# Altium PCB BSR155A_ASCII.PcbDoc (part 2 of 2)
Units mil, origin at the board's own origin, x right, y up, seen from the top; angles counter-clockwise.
Board outline 3250 x 2500 mil, 4 copper layers (Top Layer, MidLayer1, MidLayer2, Bottom Layer), stack 59.8 mil thick; 70 components, 25 nets, 149 pads, 70 vias.
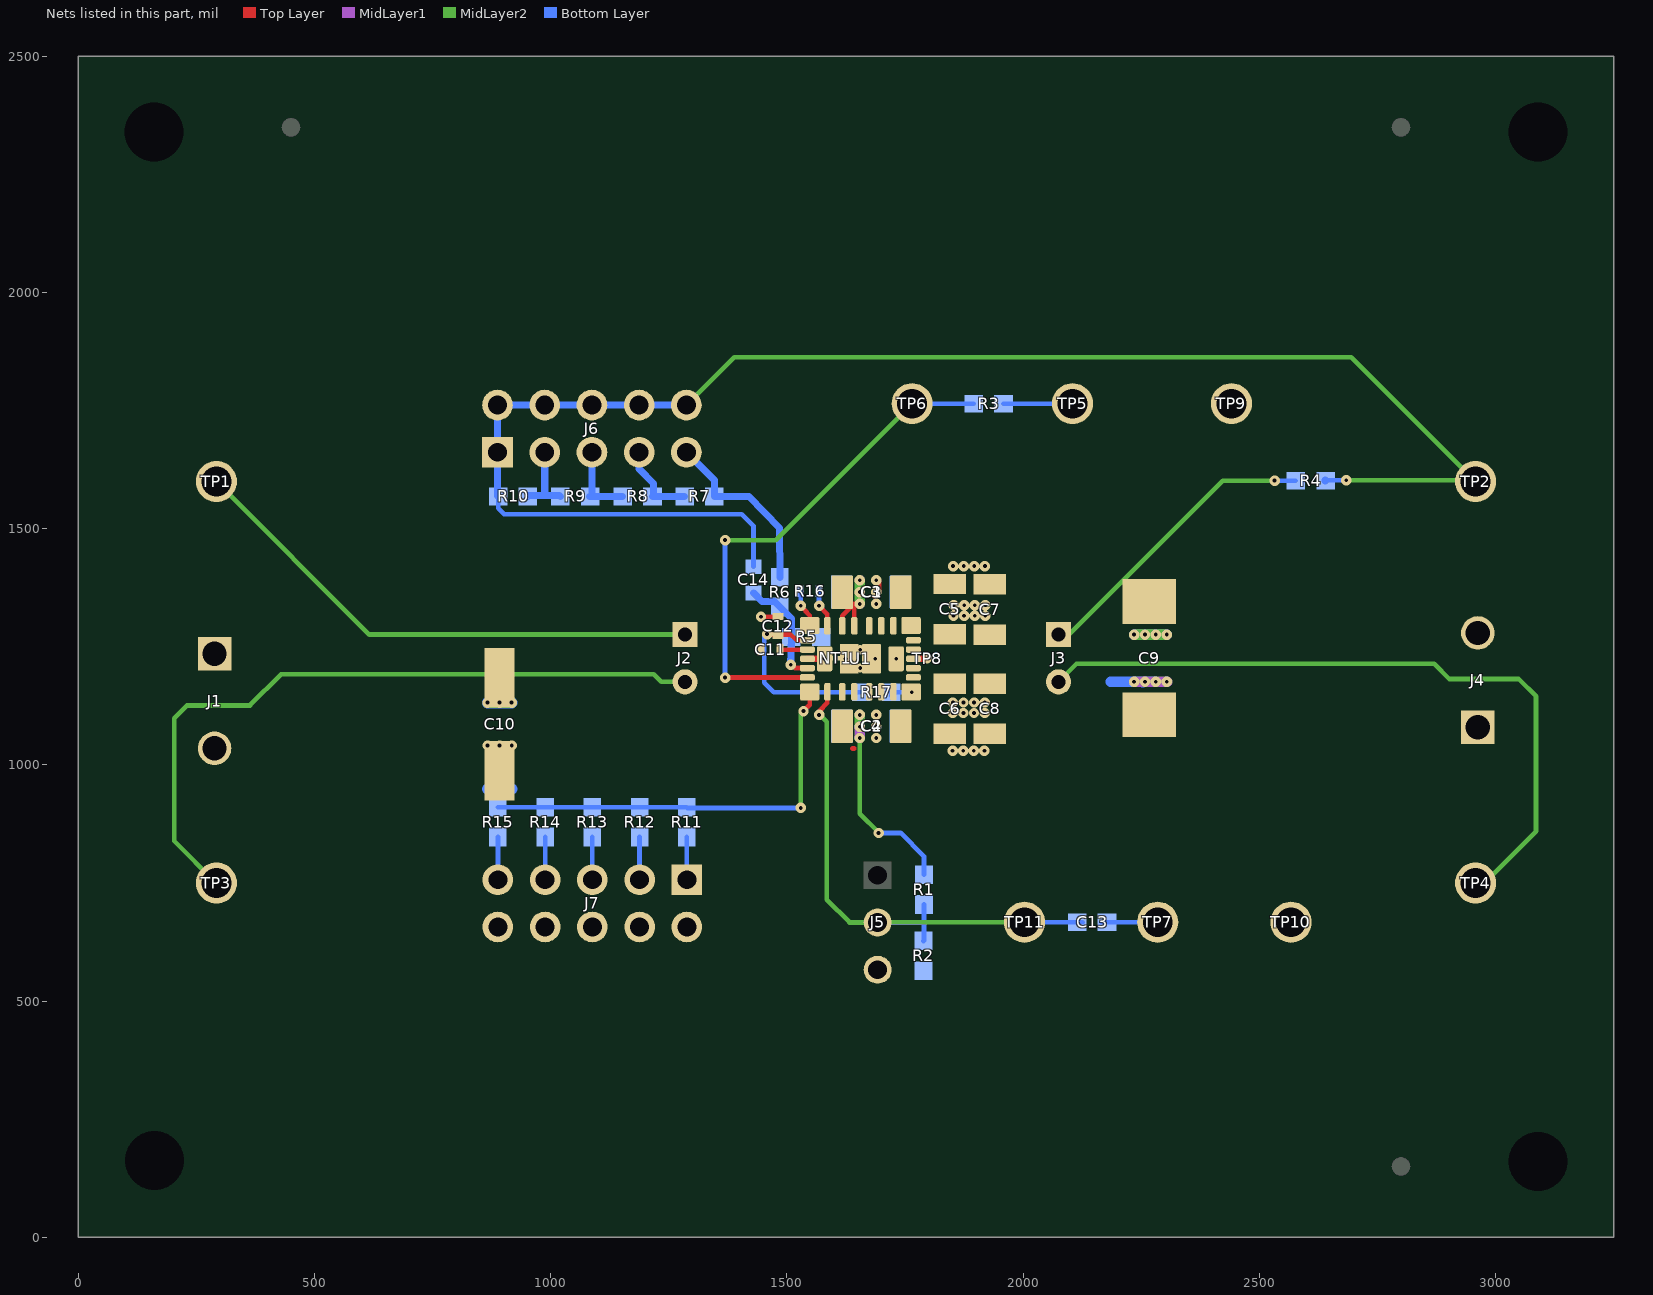
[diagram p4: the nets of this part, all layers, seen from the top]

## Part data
C1 C2 C3 C4: library part CMP-0089881-1, "4.7µF ±10% 100V Ceramic Capacitor X7S 1206 (3216 Metric)"
C5 C6 C7 C8: library part CMP-0008656-2, "CAP, CERM, 47 uF, 25 V, +/- 20%, X5R, 1206_190"
C9: library part CMP-0064986-2, "CAP, Tantalum Polymer, 330 uF, 10 V,+/- 20%, 0.035 ohm, 7343-40 SMD"
C10: library part CMP-0011204-2, "CAP, AL, 47 uF, 50 V, +/- 20%, 0.68 ohm, AEC-Q200 Grade 2, SMD"
C11: library part CMP-0006347-2, "CAP, CERM, 1 uF, 16 V, +/- 10%, X5R, 0402"
C12: library part CMP-0006608-2, "CAP, CERM, 1 uF, 25 V, +/- 10%, X5R, 0402"
C13: library part CMP-0006845-4, "CAP, CERM, 1000 pF, 50 V, +/- 5%, X7R, 0603"
C14: library part CMP-0007396-4, "CAP, CERM, 4700 pF, 16 V, +/- 10%, X7R, 0603"
FID1 FID2 FID3 FID4 FID5 FID6: library part CMP-0077181-1, "Fiducial mark.  There is nothing to buy or mount."
J1 J4: library part CMP-0074959-1, "Terminal Block, 2x1, 5.08mm, TH"
J2 J3: library part CMP-0055017-1, "Socket Strip, 2x1, 100mil, Black, Tin, TH"
J5: library part CMP-0002338-1, "Header, 100mil, 3x1, Tin, TH"
J6 J7: library part CMP-0054550-2, "Header, 100mil, 5x2, Tin, TH"
Logo1: library part CMP-0074838-1, "Texas Instrument Corporate Signature"
Logo2: library part CMP-0074844-1
Logo3: library part CMP-0074847-1, "FCC_disclaimer"
Logo4: library part CMP-0074769-1
NT1: library part CMP-0078142-3, "Single point connection between nets."
R1: library part CMP-0022408-4, "RES, 402 k, 1%, 0.1 W, AEC-Q200 Grade 0, 0603"
R2: library part CMP-0022038-4, "RES, 133 k, 1%, 0.1 W, AEC-Q200 Grade 0, 0603"
R3: library part CMP-0022447-4, "RES, 49.9 k, 1%, 0.1 W, AEC-Q200 Grade 0, 0603"
R4: library part CMP-0025754-4, "RES, 20, 5%, 0.1 W, AEC-Q200 Grade 0, 0603"
R5: library part CMP-0021998-4, "RES, 10.0 k, 1%, 0.1 W, AEC-Q200 Grade 0, 0603"
R6: library part CMP-0022066-4, "RES, 15.0 k, 1%, 0.1 W, AEC-Q200 Grade 0, 0603"
R7: library part CMP-0022634-4, "RES, 8.06 k, 1%, 0.1 W, AEC-Q200 Grade 0, 0603"
R8: library part CMP-0022081-4, "RES, 16.9 k, 1%, 0.1 W, AEC-Q200 Grade 0, 0603"
R9: library part CMP-0022237-4, "RES, 24.9 k, 1%, 0.1 W, AEC-Q200 Grade 0, 0603"
R10: library part CMP-0022430-4, "RES, 45.3 k, 1%, 0.1 W, AEC-Q200 Grade 0, 0603"
R11: library part CMP-0022249-4, "RES, 26.7 k, 1%, 0.1 W, AEC-Q200 Grade 0, 0603"
R12: library part CMP-0022089-4, "RES, 17.4 k, 1%, 0.1 W, AEC-Q200 Grade 0, 0603"
R13: library part CMP-0022042-4, "RES, 13.0 k, 1%, 0.1 W, AEC-Q200 Grade 0, 0603"
R14: library part CMP-0022637-4, "RES, 8.66 k, 1%, 0.1 W, AEC-Q200 Grade 0, 0603"
R15: library part CMP-0022560-4, "RES, 6.34 k, 1%, 0.1 W, AEC-Q200 Grade 0, 0603"
R16: library part CMP-0026827-3, "RES, 10, 5%, 0.063 W, AEC-Q200 Grade 0, 0402"
R17: library part CMP-0023343-3, "RES, 0, 1%, 0.1 W, AEC-Q200 Grade 0, 0603"
SH-J5 SH-J6 SH-J7: library part CMP-0003641-1, "Shunt, 2mm, Gold plated, Black"
TP1 TP2: library part CMP-0055147-1, "Test Point, Multipurpose, Red, TH"
TP3 TP4 TP9 TP10: library part CMP-0055148-1, "Test Point, Multipurpose, Black, TH"
TP5 TP6 TP7 TP11: library part CMP-0055149-1, "Test Point, Multipurpose, White, TH"
TP8: library part CMP-0078143-3, "TEST POINT.  No entry in BOM."
U1: library part CMP-0090663-2, "TPSM63603 Cruzline Power Module"
ZZ1: library part CMP-0077236-1
ZZ2: library part CMP-0077237-1
ZZ3: library part CMP-0077238-1
ZZ4 ZZ5 ZZ6: library part CMP-0003615-1, "This Assembly Note will show in the PcbDoc and associated outputs"

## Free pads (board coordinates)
  round 120 hole 125 unplated: 0(160,2340) 0(161,163) 0(3090,160) 0(3090,2340)

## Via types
v1: diameter 22, hole 8, Top Layer to Bottom Layer, 64 vias
v2: diameter 19.68, hole 7.87, Top Layer to Bottom Layer, 6 vias

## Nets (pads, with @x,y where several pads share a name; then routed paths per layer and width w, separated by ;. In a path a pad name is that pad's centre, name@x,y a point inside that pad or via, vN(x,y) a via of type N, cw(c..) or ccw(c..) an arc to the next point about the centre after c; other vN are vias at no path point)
1.5M: J7.7 R14.1 | length 90.5
  Bottom Layer w10: J7.7@988,757 R14.1@988,847.5
1M: J7.5 R13.1 | length 90.5
  Bottom Layer w10: J7.5@1088,757 R13.1@1088,847.5
2.5: J6.9 R6.2 R7.1 | length 398.2
  Bottom Layer w10: J6.9@1280.23,1655.11 J6.9@1287.13,1662.02
  Bottom Layer w15: J6.9@1287.13,1662.02 1346.23,1602.92 R7.1@1346.23,1568.52 1419.48,1568.52 1484,1502 R6.2@1485,1397.5
2M: J7.9 R15.1 | length 90.5
  Bottom Layer w10: J7.9@888,757 R15.1@888,847.5
3.3: J6.7 R7.2 R8.1 | length 175.2
  Bottom Layer w10: R8.1@1215.23,1568.52 R8.1@1217.73,1571.02
  Bottom Layer w15: J6.7@1187.13,1662.02 1187.13,1626.38 1217.73,1595.78 R8.1@1217.73,1571.02 ; R8.1@1215.23,1568.52 R7.2@1283.24,1568.52
5.0: J6.5 R8.2 R9.1 | length 165.1
  Bottom Layer w15: R9.1@1082.23,1568.52 R8.2@1152.24,1568.52 ; R9.1@1083.23,1568.52 1087.13,1572.42 J6.5@1087.13,1662.02
7.5: J6.3 R9.2 R10.1 | length 161.8
  Bottom Layer w15: R10.1@951.63,1568.52 953.25,1570.13 987.13,1570.13 ; J6.3@987.13,1662.02 987.13,1570.13 ; R9.2@1020.24,1568.52 1018.62,1570.13 987.13,1570.13
12: C14.2 J6.1 J6.2 J6.4 J6.6 J6.8 J6.10 R4.2 R10.2 TP2.1 | length 3401.9
  MidLayer2 w10: J6.10@1287.13,1762.02 1388.12,1863 2695,1863 TP2.1@2955.1,1602.9 ; v1(2683.9,1602.9) TP2.1@2955.1,1602.9 ; TP2.1@2958,1600 TP2.1@2955.1,1602.9
  Bottom Layer w10: R10.2@888.64,1568.52 888.64,1543.36 901,1531 1404,1531 1429,1506 C14.2@1429,1419.56 ; R4.2@2639.6,1602.9 v1(2683.9,1602.9)
  Bottom Layer w15: R10.2@888.64,1568.52 887.13,1570.02 J6.1@887.13,1662.02 J6.2@887.13,1762.02 J6.4@987.13,1762.02 J6.6@1087.13,1762.02 J6.8@1187.13,1762.02 J6.10@1287.13,1762.02 ; R4.2@2639.6,1601 2639.6,1602.9 R4.2@2640.5,1602
500k: J7.1 R11.1 | length 90.5
  Bottom Layer w10: J7.1@1288,757 R11.1@1288,847.5
750k: J7.3 R12.1 | length 90.5
  Bottom Layer w10: J7.3@1188,757 R12.1@1188,847.5
AGND: C12.2 J7.2 J7.4 J7.6 J7.8 J7.10 NT1.1 R5.1 U1.24 U1.27 | length 72.4
  Top Layer w10: v1(1445,1314) C12.2@1481,1314
  Top Layer w13: U1.24@1543.24,1224.74 v2(1579.66,1224.74)
EN: C13.2 J5.2 R1.1 R2.2 TP11.1 U1.2 | length 1190.8
  Top Layer w10: v1(1568,1106) 1568,1114 1585.57,1131.57 U1.2@1585.57,1154.86
  MidLayer2 w10: v1@1569,1106 1584,1091 1584,1088 1584.04,714.96 1632.53,666.47 J5.2@1692.07,666.47 TP11.1@2003,667
  Bottom Layer w10: J5.2@1692.07,666.47 1790,666.47 ; R2.2@1789,627.5 1790,628.5 1790,666.47 ; R1.1@1790,704.5 1790,666.47 ; TP11.1@2003,667 C13.2@2126,667
FB: C14.1 R5.2 R6.1 U1.25 | length 253.9
  Top Layer w10: v1(1508,1212) 1516.94,1205.06 U1.25@1543.24,1205.06 U1.25@1528,1205
  Bottom Layer w15: C14.1@1429,1364.44 1447.44,1346 1473.5,1346 R6.1@1485,1334.5 1509.5,1310 R5.2@1509.5,1271 v1(1508,1212)
NetC11_1: C11.1 U1.23 | length 58.2
  Top Layer w10: C11.1@1485,1244 U1.23@1543.24,1244.43
NetC13_1: C13.1 TP7.1 | length 119
  Bottom Layer w10: C13.1@2166,667 TP7.1@2285,667
NetR16_1: R16.1 U1.21 | length 81.2
  Top Layer w10: v1(1529,1337) 1548.17,1316.53 U1.21@1548.17,1295.06
  Top Layer w15: v1@1529,1335.69 v1@1529,1336
  Bottom Layer w10: R16.1@1528,1368 1529,1367 v1(1529,1337)
NetR16_2: R16.2 U1.20 | length 80.7
  Top Layer w10: v1(1568,1337) 1585.57,1319.43 U1.20@1585.57,1294.62
  Bottom Layer w10: v1(1568,1337) R16.2@1568,1368
NetTP8_1: TP8.1 U1.11 | length 29.3
  Top Layer w13: U1.11@1767.65,1224.74 TP8.1@1797,1225
PG_PU: R3.1 TP5.1 | length 146.2
  Bottom Layer w10: R3.1@1958.5,1765 TP5.1@2104.73,1765
PGND: C1.1 C2.1 C3.1 C4.1 C5.1 C6.1 C7.1 C8.1 C9.2 C10.2 C11.2 J1.2 J2.2 J3.2 J4.1 J5.3 NT1.2 R2.1 TP3.1 TP4.1 TP9.1 TP10.1 U1.5 U1.6 U1.16 U1.17 U1.28 U1.29 | length 3275.3
  Top Layer w13: v1@1686.02,1359.02 1693.54,1366.54 v1@1693.54,1388.48
  MidLayer1 w22: v1(2235,1176) v1@2305,1176
  MidLayer2 w10: TP3.1@292,750 203,839 203,1099 230,1126 363,1126 429,1192 1218,1192 1234,1176 J2.2@1284,1176 ; J3.2@2075,1176 2113.01,1214 2870,1214 2902,1182 3049,1182 3086,1145 3086,860 TP4.1@2976,750 ; TP4.1@2934,750 TP4.1@2958,750
  Bottom Layer w22: 2185.56,1176 2252.6,1176 2253.08,1175.52 2253.56,1176 v1@2275,1176
  Bottom Layer w24: 866.2,949.2 917.18,949.2
  other v1: 1850.7,1030 1873.13,1030 1895.57,1030 1918,1030 866.18,1041.18 891.68,1041.19 917.18,1041.2 1689,1057 1689,1081 1689,1106 2258,1176 2281,1176 2304,1176 1689,1341 1689,1366 1689,1391 1851.7,1421 1874.13,1421 1896.57,1421 1919,1421
  other v2: 1655.45,1205.45 1623.95,1224.74 1686.94,1224.74 1655.45,1244.03
PGOOD: R3.2 TP6.1 U1.26 | length 1107.5
  Top Layer w10: v1(1369,1185) U1.26@1543.24,1185.37
  MidLayer2 w10: v1(1369,1476) 1476,1476 TP6.1@1765,1765
  Bottom Layer w10: v1(1369,1185) v1(1369,1476) ; TP6.1@1769,1765 R3.2@1895.5,1765
RT: R11.2 R12.2 R13.2 R14.2 R15.2 U1.1 | length 895
  Top Layer w10: v1(1535,1114) 1548.17,1127.17 U1.1@1548.17,1154.43
  MidLayer2 w10: v1(1529,909) 1529,1108 v1(1535,1114)
  Bottom Layer w10: R15.2@888,910.5 R14.2@988,910.5 R13.2@1088,910.5 R12.2@1188,910.5 R11.2@1288,910.5 1289.5,909 v1(1529,909)
VIN: C1.2 C2.2 C3.2 C4.2 C10.1 J1.1 J2.1 R1.2 TP1.1 U1.3 U1.4 U1.18 U1.19 | length 1832.3
  Top Layer w10: U1.19@1617.06,1294.62 1617.06,1316.06 1642,1341 1642.65,1340.35 U1.18@1642.65,1294.62 ; 1638,1035 1642,1035
  MidLayer1 w22: v1(1654,1057) v1(1654,1081)
  MidLayer2 w10: TP1.1@292.74,1599.26 616,1276 J2.1@1284,1276 ; v1@1654,1056 1654,897 v1@1694,857
  MidLayer2 w22: v1(866.02,1132) v1(917.02,1132.02) ; v1(1654,1057) 1654,1056 v1(1654,1106) ; v1(1654,1341) v1(1654,1391)
  Bottom Layer w10: v1(1694,856) 1741,856 1790,807 R1.2@1790,767.5
  Bottom Layer w22: C4.2@1615.99,1082 C4.2@1616.99,1081
  Bottom Layer w24: v1(866.02,1132) v1(891.52,1132.01) ; v1(891.52,1132.01) v1(917.02,1132.02)
  other v1: 1654,1366
VLDOIN: C12.1 R17.2 U1.22 | length 408.8
  Top Layer w10: v1@1458,1276 1479,1276 C12.1@1481,1274 1483,1276 1508,1276 1518.33,1265.67 ; 1520.01,1264 U1.22@1543.24,1264.11
  Bottom Layer w10: v1(1458,1277) 1452,1271 1452,1174 1472,1154 R17.2@1657.5,1154
VOUT: C5.2 C6.2 C7.2 C8.2 C9.1 J3.1 J4.2 R4.1 R17.1 U1.7 U1.8 U1.9 U1.10 U1.12 U1.13 U1.14 U1.15 U1.30 | length 807.5
  MidLayer2 w10: J3.1@2075,1276 2097,1276 2423,1602 v1(2532.5,1602)
  MidLayer2 w22: v1(2235,1276) v1(2304,1276)
  Bottom Layer w10: R17.1@1720.5,1154 1752,1154 ; R17.1@1720.99,1147 R17.1@1721.99,1146 ; v1(2532.5,1602) R4.1@2576.5,1602
  Bottom Layer w22: v1(2235,1276) v1(2304,1276)
  other v1: 1851.06,1109.9 1873.49,1109.9 1895.92,1109.9 1918.35,1109.9 1851.28,1132.2 1873.71,1132.2 1896.14,1132.2 1918.58,1132.2 1764,1154 2258,1276 2281,1276 1852.57,1316 1875,1316 1897.43,1316 1919.87,1316 1852.79,1338.3 1875.22,1338.3 1897.65,1338.3 1920.09,1338.3
  other v2: 1731.24,1224.74
pads on no net: FID1.1 FID2.1 FID3.1 FID4.1 FID5.1 FID6.1 J5.1 SH-J5.0 SH-J6.0 SH-J7.0

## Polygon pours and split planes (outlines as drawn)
PGND on Top Layer "PGND" (solid, pour order 351): 3283.31,2466.14 3283.33,-33.86 33.31,-33.86 33.31,2466.14
VIN on Top Layer "VIN_L01_P348" (solid, remove dead copper, pour order 348): 1591,1410 1591,1275 1649,1275 1665,1291 1665,1408 1658,1415 1596,1415
VIN on Top Layer "VIN_L01_P342" (solid, remove dead copper, pour order 342): 1591,1174 1666,1174 1666,1033 1660,1027 1596,1027 1591,1032
VOUT on Top Layer "VOUT_L01_P341" (solid, remove dead copper, pour order 341): 1971,1349.68 1971,1099.17 1715,1099.17 1715,1349.69
VIN on MidLayer1 "Top-Vin" (solid, remove dead copper, pour order 350): 1009,991 1649,991 1665,1007 1665,1128 1645,1148 1544,1148 1544,1298 1651,1298 1665,1312 1665,1454 1651,1468 212,1468 212,1136 816,1136 853,1085 934,1085
VOUT on MidLayer1 "Top-Vout" (solid, remove dead copper, pour order 354): 2566.44,1053 1746,1053 1721,1078 1721,1371 1748,1398 2091.57,1398 2185,1471.5 3020.5,1471.5 3046,1446 3046,1220 3019.48,1193.48 2706.92,1193.48
PGND on MidLayer1 "Layer_2-PGND" (solid, remove dead copper, pour order 370): -0.85,2.63 3249.15,2.64 3249.15,2502.64 -0.85,2502.64
VOUT on MidLayer2 "VOUT_L03_P379" (solid, remove dead copper, pour order 379): 1841.72,1344.8 1846.72,1349.8 1925.72,1349.8 1930.72,1344.8 1930.72,1309.8 1924.72,1303.8 1847.72,1303.8 1841.72,1309.8
VOUT on MidLayer2 "VOUT_L03_P378" (solid, remove dead copper, pour order 378): 1840,1139 1845,1144 1924,1144 1929,1139 1929,1104 1923,1098 1846,1098 1840,1104
no net on MidLayer2 "NONET_L03_P391" (solid, remove dead copper, pour order 391): 765,793
AGND on MidLayer2 "AGND_L03_P340" (solid, remove dead copper, pour order 340): 838,596 1466,596 1527,657 1527,1114 1594,1181 1594,1291 1549,1336 1399,1336 1357,1294 1357,714 843,714 825,696 825,609
PGND on MidLayer2 "PGND" (solid, pour order 381): 3250,0 0,0.15 0,2500 3250,2500
VOUT on Bottom Layer "VOUT_L04_P376" (solid, remove dead copper, pour order 376): 1840,1139 1845,1144 1924,1144 1929,1139 1929,1104 1923,1098 1846,1098 1840,1104
VOUT on Bottom Layer "VOUT_L04_P374" (solid, remove dead copper, pour order 374): 1842,1345 1847,1350 1926,1350 1931,1345 1931,1310 1925,1304 1848,1304 1842,1310
VIN on Bottom Layer "VIN_L04_P362" (solid, remove dead copper, pour order 362): 1589,1118 1665,1118 1665,1044 1589,1044
VIN on Bottom Layer "VIN_L04_P360" (solid, remove dead copper, pour order 360): 1589,1403 1665,1403 1665,1329 1589,1329
PGND on Bottom Layer "Layer_2-PGND" (solid, remove dead copper, pour order 387): 3239.84,2503.39 -10.16,2503.38 -10.16,3.38 3239.84,3.38

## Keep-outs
Keep-Out Layer:
  lines w10: 0,-6 0,2496 3250,2496 3250,-6 0,-6
  text ".Layer_Name" at 72.5,-1858.99 h60

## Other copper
Top Layer:
  region net VOUT: 2337.14,1395.14 2204,1395.14 2204,1261 2337.14,1261
  rectangle net VIN: 854,1119 928,1249
  region net PGND: 928.2,961.2 854.2,961.2 854.2,831.2 928.2,831.2
  rectangle net PGND: 2169.94,1056.52 2303.08,1190.66
  text ".Layer_Name" at -6.24,-1858.99 h60
MidLayer1:
  text ".Layer_Name" at -6.24,-1858.99 h60
MidLayer2:
  text ".Layer_Name" at -6.24,-1858.99 h60
Bottom Layer:
  rectangle net AGND: 1552,1210 1600,1297.27
  text ".Layer_Name" at 72.5,-1858.99 h60

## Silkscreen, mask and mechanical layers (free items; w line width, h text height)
Top Overlay:
  lines w6: 1755.58,668.79 1811.58,668.79 ; 1762.58,524.79 1811.58,524.79 1811.58,543.67 ; 1762.58,805.79 1811.58,805.79 1811.58,789.67 ; 1812.58,651.67 1812.58,667.79 1812.58,688.67
  text "'.PRJ_Title'" at 1169,2279 h120
  text "PG_PU" at 2007,1873 h50
  text "PGND" at 2353,1872 h50
  text "PGOOD" at 1648,1869 h50
  text "3.3V" at 1214,1838 h50 r90
  text "2.5V" at 1314,1838 h50 r90
  text "12V" at 914,1837 h50 r90
  text "7.5V" at 1013,1835 h50 r90
  text "5.0V" at 1113,1833 h50 r90
  text "VIN" at 242,1767 h50
  text "VOUT" at 2874,1763 h50
  text "S+" at 250,1696 h50
  text "S+" at 2919.75,1695.26 h50
  text "VOUT  / SELECT" at 547,1664 h50
  text "VOUT" at 3007.5,1426 h50
  text "VIN" at 67,1424 h50
  text "+" at 2059,1423 h45
  text "+" at 2239,1416 h70
  text "+" at 378,1406 h70
  text "Vin" at 1207,1327 h50
  text "V" at 1864,1322 h50
  text "OUT" at 1929,1309.31 h30
  text "+" at 1172,1280.01 h45
  text "+" at 720,1221 h50
  text "1" at 1501,1139 h25
  text "PGND" at 50,848 h50
  text "PGND" at 3002,848 h50
  text "ON" at 1771.32,714.67 h50
  text "FSW  / SELECT" at 537,638 h50
  text "VIN" at 242,606 h50
  text "VOUT" at 2874.25,603.74 h50
  text "OFF" at 1764.58,569.79 h50
  text "S-" at 254,538 h50
  text "S-" at 2920,536 h50
  text "SYNC" at 2193,527 h50
  text "PGND" at 2487,526 h50
  text "EN" at 1968,524 h50
  text "ENABLE" at 1577.32,427.67 h50
  text "1.0MHz" at 1106,342 h50 r90
  text "1.5MHz" at 1008,341 h50 r90
  text "2.0MHz" at 909,331 h50 r90
  text "500kHz" at 1311.42,327.11 h50 r90
  text "750kHz" at 1209,326 h50 r90
  text "'.PRJ_Number'.PCB_Rev" at 2123,66 h45
  text ".Layer_Name" at 72.5,-1858.99 h60
Bottom Overlay:
  text ".Layer_Name" at 72.5,-1858.99 h60
Top Paste:
  text ".Layer_Name" at 72.5,-1858.99 h60
Bottom Paste:
  text ".Layer_Name" at 72.5,-1858.99 h60
Top Solder:
  text ".Layer_Name" at 72.5,-1858.99 h60
  text ".Layer_Name" at 72.5,-1858.99 h60
Bottom Solder:
  text ".Layer_Name" at 72.5,-1858.99 h60
Drill Guide:
  text ".Layer_Name" at 72.5,-1858.99 h60
M1 Board Outline:
  the board outline again, w4
  text ".Layer_Name" at -6.24,-1858.99 h60
M2 Board Dimensions:
  rectangle: -379.5,-1400.5 -4.5,-1275.5
  rectangle: -504.5,-1275.5 -379.5,-1150.5
  lines w7: -504.5,-1275.5 495.5,-1275.5 ; -379.5,-1400.5 -379.5,-1150.5 ; -254.5,-1400.5 -254.5,-1150.5 ; -4.5,-1400.5 -4.5,-1150.5 ; 245.5,-1400.5 245.5,-1150.5 ; -504.5,-1400.5 -504.5,-1150.5 495.5,-1150.5 495.5,-1400.5 -504.5,-1400.5
  text ".Layer_Name" at -6.24,-1858.99 h60
M3 3D STEP Top:
  text ".Layer_Name" at -6.24,-1858.99 h60
M4 3D STEP Bottom:
  text ".Layer_Name" at -6.24,-1858.99 h60
M5 Assembly Top:
  lines w10: -816.18,-1930.67 5033.85,-1930.67 ; -816.18,-1727.33 5033.85,-1727.33 ; -816.18,-1524 -816.18,-2134 3188.81,-2134 ; 759.82,-2134 -815.68,-2134 -815.68,-1524 5033.85,-1524 5033.85,-2134 2712.44,-2134 ; 1467.71,-2134 1467.71,-1524 ; 2498.49,-1727.33 2498.49,-1524 ; 3220.38,-1727.33 3220.38,-1524 ; 3724.27,-2140.5 3724.27,-1937.67
  text "COMPONENTS MARKED 'DNP' SHOULD NOT BE POPULATED." at 526.95,-1319 h60
  text "ASSEMBLY VARIANT:" at 526.45,-1434.5 h60
  text ".VariantName" at 1554.58,-1434.5 h60
  text "PCB VIEWED FROM TOP SIDE" at -772.37,-1656.17 h60
  text "BOARD #:" at 1511.22,-1656.17 h60
  text ".PRJ_Number" at 1970.1,-1656.17 h60
  text "REV:" at 2657.12,-1656.17 h60
  text ".PCB_Rev" at 2889.57,-1656.17 h60
  text "SVN REV:" at 3290.4,-1656.17 h60
  text ".VersionControl_RevNumber" at 3784.59,-1656.17 h60
  text "TID #:" at 1511.22,-1859.5 h60
  text ".TID" at 1970.1,-1859.5 h60
  text "PLOT NAME =" at -772.37,-2064.84 h60
  text ".plot_File_Name" at -6.24,-2064.84 h60
  text "GENERATED    :" at 1513.22,-2064.84 h60
  text ".Print_Date" at 2237.05,-2064.84 h60
  text ".Print_Time" at 2828.25,-2064.84 h60
  text "TEXAS INSTRUMENTS" at 3895.9,-2064.84 h60
M6 Assembly Bottom:
  lines w10: -816.68,-1727.83 5033.85,-1727.83 ; -814.68,-1931.17 5033.85,-1931.17 ; 508.64,-2141 508.64,-1938.17 ; 1051.9,-1727.83 1051.9,-1524.5 ; 1540.16,-2134.5 5033.85,-2134.5 3575.46,-2134.5 ; 1780.32,-2134.5 -816.68,-2134.5 -816.68,-1524.5 5033.85,-1524.5 ; 1793.47,-1727.83 1793.47,-1524.5 ; 2824.25,-2134.5 2824.25,-1524.5 ; 5032.85,-2134.5 5032.85,-1524.5 ; 5033.35,-2134.5 5033.35,-1524.5
  text "COMPONENTS MARKED 'DNP' SHOULD NOT BE POPULATED." at 5199.86,-1318.5 h60
  text ".VariantName" at 3860.59,-1434.5 h60
  text "ASSEMBLY VARIANT:" at 4860.22,-1434.5 h60
  text ".VersionControl_RevNumber" at 531,-1656.67 h60
  text "SVN REV:" at 1017.32,-1656.67 h60
  text ".PCB_Rev" at 1422.08,-1656.67 h60
  text "REV:" at 1662.4,-1656.67 h60
  text "BOARD #:" at 2729.57,-1656.67 h60
  text "PCB VIEWED FROM BOTTOM SIDE" at 4989.53,-1656.67 h60
  text ".PRJ_Number" at 2311,-1661 h60
  text ".TID" at 2282.49,-1860 h60
  text "TID #:" at 2729.57,-1860 h60
  text "TEXAS INSTRUMENTS" at 340.95,-2065.34 h60
  text ".Print_Time" at 1522.77,-2065.34 h60
  text ".Print_Date" at 2141.53,-2065.34 h60
  text "GENERATED    :" at 2924.42,-2065.34 h60
  text ".plot_File_Name" at 4321.83,-2065.34 h60
  text "PLOT NAME =" at 4989.53,-2065.34 h60
M9 Title Sheet:
  lines w5: -1016,-1134 -816,-1134 ; -1016,766 -816,766 ; -1016,2666 -816,2666 ; 1184,-2834 10284,-2834 ; 1859,-3034 1859,-2834 ; 1859,4366 1859,4566 ; 4734,-3034 4734,-2834 ; 4734,4366 4734,4566 ; 7609,-3034 7609,-2834 ; 7609,4366 7609,4566 ; 10284,-1634 10284,-2834 ; 10284,-1134 10484,-1134 ; 10284,766 10484,766 ; 10284,2666 10484,2666 ; 10284,-2834 10284,4366 -816,4366 -816,-2834 10284,-2834 ; -1016,-3034 -1016,4566 10484,4566 10484,-3034 -1016,-3034
  lines w10: -816,-2224 7279,-2224 ; 592,-2834 592,-2224 ; 7279,-2524 10279,-2524 ; 7279,-1924 10279,-1924 ; 7279,-1330 7279,-1624 ; 7280,-1330 10280,-1330 ; 8784,-2824 8784,-2224 ; 10279,-2224 7279,-2224 ; 10279,-1624 7279,-1624 ; 7279,-2224 7279,-2834 7279,-2224 ; 7279,-2224 7279,-1624
  text "1" at 411,4431 h70
  text "2" at 3271,4431 h70
  text "3" at 6151,4431 h70
  text "4" at 9021,4431 h70
  text "A" at -941,3525 h70
  text "A" at 10359,3525 h70
  text "B" at -941,1633 h70
  text "B" at 10359,1633 h70
  text "C" at -941,-277 h70
  text "C" at 10359,-277 h70
  text "PROJECT TITLE:" at 7319,-1423 h45
  text ".PRJ_Title" at 7369,-1556.33 h60
  text "DESIGNED FOR:" at 7319,-1724 h45
  text ".PRJ_Customer" at 7369,-1864 h70
  text "FILE NAME:" at 7319,-2024 h45
  text ".PCB_File_Name_No_Path" at 7369,-2144 h70
  text "D" at -941,-2167 h70
  text "D" at 10359,-2167 h70
  text "Texas Instruments (TI) and/or its licensors do not warrant the accuracy or completeness of this specification" at 710.5,-2313.84 h60
  text "ENGINEER:" at 7319,-2314 h45
  text "LAYOUT BY:" at 8824,-2314 h45
  text "or any information contained therein. TI and/or its licensors do not warrant that this design will meet" at 665.51,-2426.5 h60
  text ".PRJ_Engineer" at 7369,-2468.99 h70
  text ".PCB_Layout" at 8874.5,-2468.99 h70
  text "the specifications, will be suitable for your application or fit for any particular purpose, or will operate in" at 665.51,-2539.17 h60
  text "ALTIUM DESIGNER VERSION:" at 8824,-2624 h45
  text "an implementation. TI and/or its licensors do not warrant that the design is production worthy. You should" at 665.51,-2651.83 h60
  text ".print_Scale" at 7369,-2757.33 h70
  text ".Application_BuildNumber" at 8874.5,-2757.33 h70
  text "completely validate and test your design implementation to confirm the system functionality for your application." at 710.5,-2764.5 h60
  text "1" at 411,-2969 h70
  text "2" at 3271,-2969 h70
  text "3" at 6151,-2969 h70
  text "4" at 9021,-2969 h70
M10 Fab Notes:
  drawing of 192 lines, arcs and shapes, not listed
  text "DESIGN INFORMATION" at 8358.52,4155.17 h60
  text "MIN. TRACK WIDTH:" at 7713.96,4023.05 h60
  text "mil" at 8965.46,4023.05 h60
  text "10" at 8744,4018.24 h60
  text "MIN. CLEARANCE:" at 7713.96,3898.92 h60
  text "mil" at 8965.46,3898.92 h60
  text "4" at 8744,3895.11 h60
  text "MIN. VIA PAD SIZE:" at 7713.96,3774.8 h60
  text "mil" at 8965.46,3774.8 h60
  text "22" at 8744,3770 h60
  text "0.05mm (2MIL)" at 8408.96,3644.9 h60
  text "MINIMUM ANNULAR RING" at 7384.73,3636.67 h60
  text "EXTERNAL" at 9116.96,3636.67 h60
  text "PER" at 7584.73,3526.55 h60
  text "IPC-D-275 CLASS 2 LEVEL C" at 7804.73,3526.54 h60
  text "MIL, HOLES" at 9292.96,3426.07 h60
  text "+/-" at 8900.5,3417.48 h60
  text "+/-" at 9754.5,3417.48 h60
  text "REGISTRATION TOLERANCES:" at 7384.73,3416.42 h60
  text "METAL" at 8584.5,3416.42 h60
  text "5" at 9160.7,3416.42 h60
  text "3" at 9993.7,3416.42 h60
  text "MIL" at 10109.96,3416.42 h60
  text "HOLE SIZE TOLERANCE (UNLESS OTHERWISE SPECIFIED):" at 7384.73,3318.1 h60
  text "+/-" at 9754.5,3315.23 h60
  text "3" at 9993.7,3314.17 h60
  text "MIL" at 10109.96,3314.17 h60
  text "MATERIAL:" at 7309.96,3176.52 h60
  text "FR-4 High Tg" at 8296.4,3048 h60
  text "X" at 8151.96,3040.01 h60
  text "FR-408" at 7730.96,3035.49 h60
  text "OTHER" at 9218.96,3035.49 h60
  text "62 MIL (1.6mm) +/-10%" at 8051.06,2892.46 h60
  text "X" at 7930.96,2890.01 h60
  text "THICKNESS:" at 7384.73,2884.24 h60
  text "OTHER" at 9335.96,2884.24 h60
  text "TOLERANCE:" at 7384.73,2745.92 h60
  text "X" at 8232.96,2745.92 h60
  text "ANSI IPC-6012 TYPE 3 CLASS 2" at 8410.98,2745.92 h60
  text "OTHER +/-" at 8410.96,2601.73 h60
  text "BOW & TWIST:" at 7384.73,2456.54 h60
  text "X" at 8232.96,2456.54 h60
  text "ANSI IPC-6012 TYPE 3 CLASS 2" at 8410.98,2456.54 h60
  text "OTHER +/-" at 8410.96,2309.85 h60
  text "DRILLING:" at 7309.96,2179.23 h60
  text "NC_DRILL FILES" at 9070.96,2074.04 h60
  text "REFERENCE:" at 7384.73,2070.1 h60
  text "X" at 8041.96,2070.01 h60
  text "AS SHOWN" at 8219.96,2070.1 h60
  text "X" at 8942.96,2070.1 h60
  text "OTHER" at 9368.96,1927.85 h60
  text "PTH COPPER THICKNESS:" at 7384.41,1924.32 h60
  text "X" at 8523.64,1924.32 h60
  text "20-30 um" at 8651.64,1924.32 h60
  text "BOARD FINISH:" at 7309.96,1776.73 h60
  text "SILKSCREEN:" at 7465.18,1666.6 h60
  text "X" at 8422.96,1666.6 h60
  text "TOP" at 8539.96,1666.6 h60
  text "X" at 8932.96,1666.6 h60
  text "BOTTOM" at 9050.96,1666.6 h60
  text "SILKSCREEN COLOR:" at 7465.18,1511.41 h60
  text "X" at 8421.96,1511.41 h60
  text "WHITE" at 8539.96,1511.41 h60
  text "OTHER" at 9050.96,1511.41 h60
  text "X" at 8552.96,1367.96 h60
  text "GREEN" at 8670.96,1367.96 h60
  text "OTHER" at 9288.96,1367.96 h60
  text "SOLDER RESIST COLOR:" at 7465.18,1361.1 h60
  text "MATTE" at 8670.96,1213.71 h60
  text "SEMI-GLOSS" at 9288.5,1213.07 h60
  text "X" at 9147,1205 h60
  text "IMMERSION GOLD (ENIG)" at 8370.96,1040.94 h60
  text "ENEPIG" at 9708.5,1033.72 h60
  text "SURFACE FINISH:" at 7309.96,1032.72 h60
  text "X" at 8192.96,1032.72 h60
  text "IMM. TIN/SILVER OR EQUIV" at 7639.5,895.4 h60
  text "OTHER" at 9070.96,891.47 h60
  text "ARRAY/PANEL:" at 7309.96,736.09 h60
  text "CUT AND TRIM PER M1 BOARD OUTLINE" at 8370.96,727.87 h60
  text "N.C. ROUTE" at 8370.96,591.9 h60
  text "X" at 9058.96,591.9 h60
  text "V. SCORE" at 9236.96,591.9 h60
  text "CERTIFICATION:" at 7309.96,462.77 h60
  text "MATERIALS AND WORKMANSHIP FOR ALL PCBS" at 8034.96,462.77 h60
  text "TO MEET OR EXCEED THE REQUIREMENTS OF:" at 8034.96,368.71 h60
  text "X" at 7672.47,240.08 h60
  text "ANSI IPC-A-600F CLASS ->" at 7800.46,240.08 h60
  text "X" at 9448.47,240.08 h60
  text "2" at 9558.46,240.08 h60
  text "1" at 9243.46,238.58 h60
  text "3" at 9912.46,238.58 h60
  text "X" at 8484.47,92.39 h60
  text "RoHS" at 8612.46,92.39 h60
  text "OTHER" at 9256.86,92.39 h60
  text "PER ORDER" at 9653.92,92.39 h60
  text "ALL BOARDS MUST MEET OR EXCEED UL94-V0 REQUIREMENTS." at 7337.5,-61.43 h60
  text "PCB MUST BEAR THE UL94V-0 UL REGISTERED MATERIAL ID NUMBER" at 7337.5,-177.5 h60
  text "ADDITIONAL REQUIREMENTS:" at 7309.96,-346.92 h60
  text "MICROSECTION:" at 7384.73,-454.05 h60
  text "YES" at 8290.46,-454.05 h60
  text "REQUIRED" at 9151.96,-598.38 h60
  text "BARE BOARD ELEC. TEST:" at 7384.73,-601.24 h60
  text "NONE" at 8690.46,-601.24 h60
  text "X" at 9033.96,-601.24 h60
  text "PER ORDER" at 9743.96,-601.24 h60
  text "X" at 7378.96,-753.24 h60
  text "7.87 MIL VIAS REQUIRE NON-CONDUCTIVE FILL AND PLANARIZE" at 7440,-807 h59
  text "XX MIL VIAS REQUIRE CONDUCTIVE FILL AND PLANARIZE" at 7501.88,-910.16 h60
  text "OUTER XX MIL TRACES REQUIRE 50 OHM SINGLE-ENDED IMPEDANCE" at 7500.89,-1073.54 h58
  text "LAYER 2 & 3 (INNER LAYERS) XX MIL WIDE, XX MIL SPACE / TRACES REQUIRE 100 OHM DIFFERENTIAL IMPEDANCE" at 7492.89,-1309.26 h60
  text ".Layer_Name" at -6.24,-1858.99 h60
M11 Gerber Information:
  lines w10: -816.18,-1930.67 5033.85,-1930.67 ; -816.18,-1727.33 5033.85,-1727.33 ; -816.18,-1524 -816.18,-2134 3188.81,-2134 ; 759.82,-2134 -815.68,-2134 -815.68,-1524 5033.85,-1524 5033.85,-2134 2712.44,-2134 ; 1467.71,-2134 1467.71,-1524 ; 2498.49,-1727.33 2498.49,-1524 ; 3220.38,-1727.33 3220.38,-1524 ; 3724.27,-2140.5 3724.27,-1937.67
  text "ALL ARTWORK VIEWED FROM TOP SIDE" at -772.37,-1656.17 h60
  text "BOARD #:" at 1511.22,-1656.17 h60
  text ".PRJ_Number" at 1970.1,-1656.17 h60
  text "REV:" at 2657.12,-1656.17 h60
  text ".PCB_Rev" at 2889.57,-1656.17 h60
  text "SVN REV:" at 3290.4,-1656.17 h60
  text ".VersionControl_RevNumber" at 3784.59,-1656.17 h60
  text "LAYER NAME =" at -772.37,-1858.99 h60
  text "TID #:" at 1511.22,-1859.5 h60
  text ".TID" at 1970.1,-1859.5 h60
  text "PLOT NAME =" at -772.37,-2064.84 h60
  text ".plot_File_Name" at -6.24,-2064.84 h60
  text "GENERATED    :" at 1513.22,-2064.84 h60
  text ".Print_Date" at 2237.05,-2064.84 h60
  text ".Print_Time" at 2828.25,-2064.84 h60
  text "TEXAS INSTRUMENTS" at 3895.9,-2064.84 h60
M12 Stackup:
  drawing of 251 lines, arcs and shapes, not listed
  text "Layer" at 4163.48,4087 h50
  text "Name" at 4449.01,4087 h50
  text "Material" at 5081.62,4087 h50
  text "Thickness" at 5669.94,4087 h50
  text "Constant" at 6093.54,4087 h50
  text "Board Layer Stack" at 6499.53,4087 h50
  text "1" at 4163.48,3987 h50
  text "Top Overlay" at 4449.01,3987 h50
  text "2" at 4163.48,3887 h50
  text "Top Solder" at 4449.01,3887 h50
  text "Solder Resist" at 5081.62,3887 h50
  text "0.40mil" at 5669.94,3887 h50
  text "3.5" at 6093.54,3887 h50
  text "3" at 4163.48,3787 h50
  text "Top Layer" at 4449.01,3787 h50
  text "Copper" at 5081.62,3787 h50
  text "1.40mil" at 5669.94,3787 h50
  text "4" at 4163.48,3687 h50
  text "Dielectric1" at 4449.01,3687 h50
  text "FR-4 High Tg" at 5081.62,3687 h50
  text "5.00mil" at 5669.94,3687 h50
  text "4.2" at 6093.54,3687 h50
  text "5" at 4163.48,3587 h50
  text "MidLayer1" at 4449.01,3587 h50
  text "Copper" at 5081.62,3587 h50
  text "2.80mil" at 5669.94,3587 h50
  text "6" at 4163.48,3487 h50
  text "Dielectric2" at 4449.01,3487 h50
  text "FR-4 High Tg" at 5081.62,3487 h50
  text "40.00mil" at 5669.94,3487 h50
  text "4.2" at 6093.54,3487 h50
  text "7" at 4163.48,3387 h50
  text "MidLayer2" at 4449.01,3387 h50
  text "Copper" at 5081.62,3387 h50
  text "2.80mil" at 5669.94,3387 h50
  text "8" at 4163.48,3287 h50
  text "Dielectric3" at 4449.01,3287 h50
  text "FR-4 High Tg" at 5081.62,3287 h50
  text "5.00mil" at 5669.94,3287 h50
  text "4.2" at 6093.54,3287 h50
  text "9" at 4163.48,3187 h50
  text "Bottom Layer" at 4449.01,3187 h50
  text "Copper" at 5081.62,3187 h50
  text "2.80mil" at 5669.94,3187 h50
  text "10" at 4163.48,3087 h50
  text "Bottom Solder" at 4449.01,3087 h50
  text "Solder Resist" at 5081.62,3087 h50
  text "0.40mil" at 5669.94,3087 h50
  text "3.5" at 6093.54,3087 h50
  text "11" at 4163.48,2987 h50
  text "Bottom Overlay" at 4449.01,2987 h50
  text "(For Reference Only)" at 5093,2818 h75
  text ".Layer_Name" at -6.24,-1858.99 h60
M13 Component Bodies Top:
  text ".Layer_Name" at -6.24,-1858.99 h60
M14 Component Bodies Bottom:
  text ".Layer_Name" at -6.24,-1858.99 h60
M15 Courtyards Top:
  text ".Layer_Name" at -6.24,-1858.99 h60
M16 Courtyards Bottom:
  text ".Layer_Name" at -6.24,-1858.99 h60
Drill Drawing:
  circle w10: c3613.45,1973.28 r32.29
  lines w10: 3581.16,923.83 3645.74,923.83 3645.74,988.42 3581.16,988.42 3581.16,923.83 ; 3581.16,1069.14 3581.16,1085.29 3597.31,1101.43 3581.16,1117.58 3581.16,1133.72 3597.31,1133.72 3613.45,1117.58 3629.6,1133.72 3645.74,1133.72 3645.74,1117.58 3629.6,1101.43 3645.74,1085.29 3645.74,1069.14 3629.6,1069.14 3613.45,1085.29 3597.31,1069.14 3581.16,1069.14 ; 3581.16,1279.03 3645.74,1279.03 3613.45,1214.45 3581.16,1279.03 ; 3581.16,1359.76 3613.45,1375.9 3645.74,1359.76 3629.6,1392.05 3645.74,1424.34 3613.45,1408.2 3581.16,1424.34 3597.31,1392.05 3581.16,1359.76 ; 3581.16,1521.21 3597.31,1521.21 3613.45,1505.07 3629.6,1521.21 3645.74,1521.21 3629.6,1537.36 3645.74,1553.5 3629.6,1553.5 3613.45,1569.65 3597.31,1553.5 3581.16,1553.5 3597.31,1537.36 3581.16,1521.21 ; 3581.16,1682.67 3613.45,1650.38 3645.74,1682.67 3613.45,1714.96 3581.16,1682.67 ; 3581.16,1795.68 3645.74,1795.68 3645.74,1860.26 3581.16,1860.26 3581.16,1795.68 ; 3594.08,1808.6 3632.83,1808.6 3632.83,1847.35 3594.08,1847.35 3594.08,1808.6
  lines w12: 3523.14,880.24 7184.13,880.24 ; 3523.14,2042.71 7184.13,2042.71 ; 3917.71,734.93 3917.71,2188.02 ; 4267.1,734.93 4267.1,2188.02 ; 4955.33,734.93 4955.33,2188.02 ; 5257.93,734.93 5257.93,2188.02 ; 5695.91,734.93 5695.91,2188.02 ; 6427.69,734.93 6427.69,2188.02 ; 3523.14,734.93 7184.13,734.93 7184.13,2188.02 3523.14,2188.02 3523.14,734.93
  text "DRILL TABLE" at 5064,2411 h75
  text "Symbol" at 3610.33,2086.3 h84
  text "Count" at 3961.31,2086.3 h84
  text "Hole Size" at 4310.69,2086.3 h84
  text "Plated" at 4998.92,2086.3 h84
  text "Hole Type" at 5301.52,2086.3 h84
  text "Hole Tolerance (+)" at 5739.5,2086.3 h84
  text "Hole Tolerance (-)" at 6471.29,2086.3 h84
  text "6" at 3961.31,1940.99 h70
  text "7.87mil (0.200mm)" at 4310.69,1940.99 h70
  text "PTH" at 4998.92,1940.99 h70
  text "Round" at 5301.52,1940.99 h70
  text "31" at 3961.31,1795.68 h70
  text "8.00mil (0.203mm)" at 4310.69,1795.68 h70
  text "PTH" at 4998.92,1795.68 h70
  text "Round" at 5301.52,1795.68 h70
  text "3.00mil (0.076mm)" at 6471.29,1795.68 h70
  text "33" at 3961.31,1650.38 h70
  text "8.00mil (0.203mm)" at 4310.69,1650.38 h70
  text "PTH" at 4998.92,1650.38 h70
  text "Round" at 5301.52,1650.38 h70
  text "3.00mil (0.076mm)" at 5739.5,1650.38 h70
  text "3.00mil (0.076mm)" at 6471.29,1650.38 h70
  text "4" at 3961.31,1505.07 h70
  text "29.53mil (0.750mm)" at 4310.69,1505.07 h70
  text "PTH" at 4998.92,1505.07 h70
  text "Round" at 5301.52,1505.07 h70
  text "23" at 3961.31,1359.76 h70
  text "40.00mil (1.016mm)" at 4310.69,1359.76 h70
  text "PTH" at 4998.92,1359.76 h70
  text "Round" at 5301.52,1359.76 h70
  text "4" at 3961.31,1214.45 h70
  text "51.18mil (1.300mm)" at 4310.69,1214.45 h70
  text "PTH" at 4998.92,1214.45 h70
  text "Round" at 5301.52,1214.45 h70
  text "10" at 3961.31,1069.14 h70
  text "63.00mil (1.600mm)" at 4310.69,1069.14 h70
  text "PTH" at 4998.92,1069.14 h70
  text "Round" at 5301.52,1069.14 h70
  text "4" at 3961.31,923.83 h70
  text "125.00mil (3.175mm)" at 4310.69,923.83 h70
  text "NPTH" at 4998.92,923.83 h70
  text "Round" at 5301.52,923.83 h70
  text "115 Total" at 3961.31,778.53 h70
  text ".Layer_Name" at -6.24,-1858.99 h60
Mechanical 17:
  text ".Layer_Name" at -6.24,-1858.99 h60
Mechanical 18:
  text ".Layer_Name" at -6.24,-1858.99 h60
Mechanical 19:
  text ".Layer_Name" at -2.3,-1862.93 h60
